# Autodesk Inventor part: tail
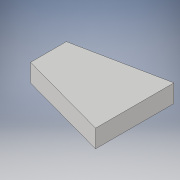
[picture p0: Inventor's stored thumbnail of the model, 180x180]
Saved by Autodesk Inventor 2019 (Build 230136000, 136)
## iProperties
Created: 2020-07
Part Number: tail
Material: 一般
Document SubType Name: Modeling
Designer: kikut
Density: 1 g/cm^3
Appearance: 既定
Author: kikut
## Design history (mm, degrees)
sketch "スケッチ1"
  geometry: L1 (0, -0.02)-(0, 0.02); L2 (0.02, 0)-(-0.12, 0) reference; L3 (0, 0.02)-(-0.05, 0.009); L4 (-0.05, 0.009)-(-0.1, 0.023); L5 (-0.1, 0.023)-(-0.1, -0.021); L6 (-0.1, -0.021)-(-0.05, -0.011); L7 (-0.05, -0.011)-(0, -0.02); 1 further point
  constraints: 12 end point, 1 parallel, 1 point on line
  dimensions: "d0" = 0.04 distance of L1.start L1.end; "d1" = 90 deg angle of L1 L2; "d2" = 0.1 distance between parallel lines of L5 L1; "d3" = 0.05 distance from line of L3.end L1; "d4" = 0.05 distance from line of L6.end L1; "d5" = 0.02 distance of L3.end L6.end
extrude "押し出し1" new body sketch "スケッチ1" stored distance "d6" = 0.01; taper "d7" = 0 deg
sketch "スケッチ2"
  geometry: L1 (-0.01, 0.03)-(0.05, 0.03); L2 (0.05, 0.03)-(0.05, -0.03); L3 (0.05, -0.03)-(-0.01, -0.03); L4 (-0.01, -0.03)-(-0.01, 0.03); L5 (0, 0.02)-(0, -0.02) reference; 1 further point
  constraints: 8 end point, 2 parallel, 1 horizontal, 1 perpendicular
  dimensions: "d8" = 0.05 distance between parallel lines of L2 L5; "d9" = 0.01 distance between parallel lines of L5 L4; "d10" = 0.06 distance of L3.end L1.start; "d11" = 0.03 distance from line of L1 point (0, 0)
extrude "押し出し2" cut sketch "スケッチ2" distance "d12" = 10; taper "d13" = 0 deg
node "ソリッド1"
